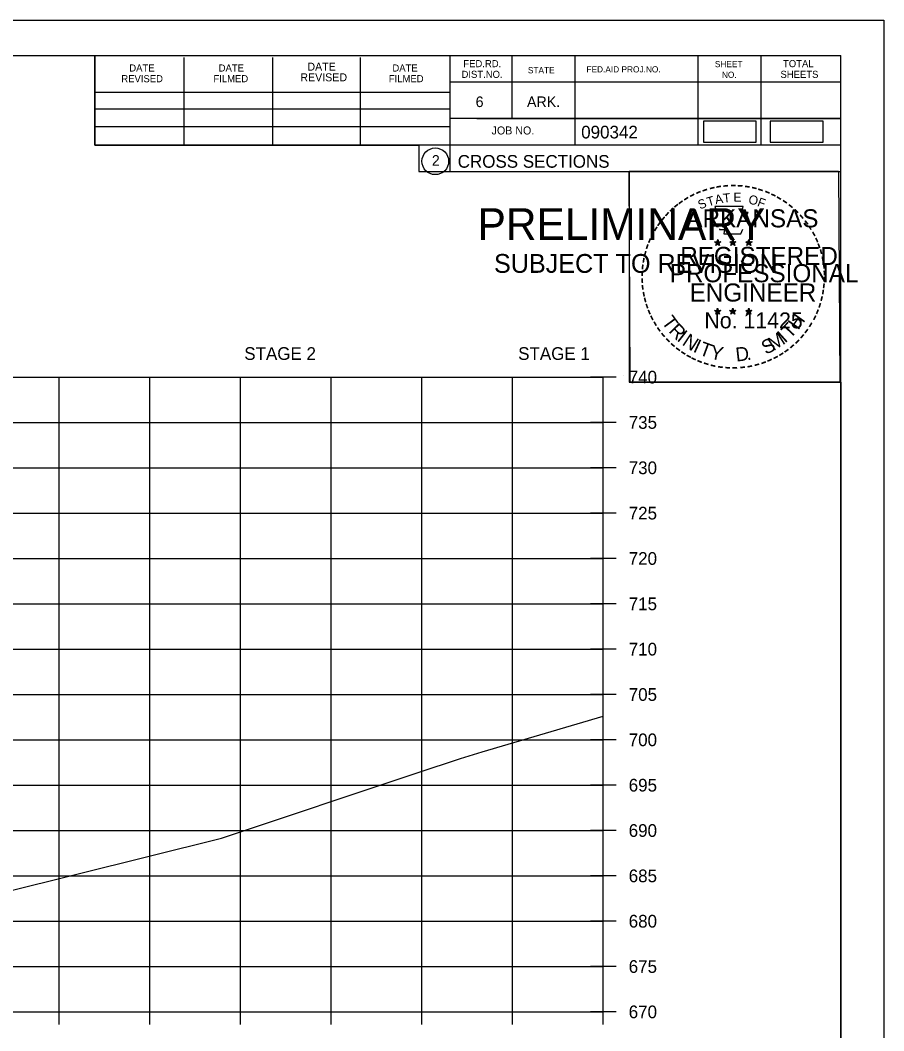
# Model space of a CAD drawing. Extents: x 1370515 to 1370849, y 383299 to 386073.
# Drawn here: x 1370753.5 to 1370848.7, y 383828 to 383939.4 of the extents above; entities that cross this region are included whole.
import ezdxf

# ---------------------------------------------------------------- set-up
doc = ezdxf.new("R2010")
doc.units = 0
for name, color, linetype in [('R_Axis', 7, 'Continuous'), ('R_Axis Annot', 7, 'Continuous'), ('R_Border', 7, 'Continuous'), ('R_Border PE', 7, 'Continuous'), ('R_Border Prem', 7, 'Continuous'), ('R_Detour', 7, 'Continuous'), ('R_Exist Surface', 7, 'Continuous'), ('R_Grid', 7, 'Continuous'), ('R_No Plot', 7, 'Continuous')]:
    doc.layers.add(name, color=color, linetype=linetype)

msp = doc.modelspace()

# ---------------------------------------------------------------- linework, layer by layer
at = {"layer": 'R_Axis'}
for p, q in [((1370819.2, 383900.08), (1370816.4, 383900.08)), ((1370817.8, 383830.08), (1370817.8, 383900.08)), ((1370819.2, 383895.08), (1370816.4, 383895.08)), ((1370819.2, 383890.08), (1370816.4, 383890.08)), ((1370819.2, 383885.08), (1370816.4, 383885.08)), ((1370819.2, 383880.08), (1370816.4, 383880.08)), ((1370819.2, 383875.08), (1370816.4, 383875.08)), ((1370819.2, 383870.08), (1370816.4, 383870.08)), ((1370819.2, 383865.08), (1370816.4, 383865.08)), ((1370819.2, 383860.08), (1370816.4, 383860.08)), ((1370819.2, 383855.08), (1370816.4, 383855.08)), ((1370819.2, 383850.08), (1370816.4, 383850.08)), ((1370819.2, 383845.08), (1370816.4, 383845.08)), ((1370819.2, 383840.08), (1370816.4, 383840.08)), ((1370819.2, 383835.08), (1370816.4, 383835.08)), ((1370757.8, 383828.68), (1370757.8, 383831.48)), ((1370767.8, 383828.68), (1370767.8, 383831.48)), ((1370777.8, 383828.68), (1370777.8, 383831.48)), ((1370787.8, 383828.68), (1370787.8, 383831.48)), ((1370797.8, 383828.68), (1370797.8, 383831.48)), ((1370807.8, 383828.68), (1370807.8, 383831.48)), ((1370817.8, 383828.68), (1370817.8, 383831.48)), ((1370537.8, 383830.08), (1370817.8, 383830.08)), ((1370819.2, 383830.08), (1370816.4, 383830.08))]:
    msp.add_line(p, q, dxfattribs=at)
at = {"layer": 'R_Border'}
for p, q in [((1370527.8, 383935.54), (1370843.98, 383935.54)), ((1370761.72, 383925.66), (1370761.72, 383935.54)), ((1370800.88, 383935.54), (1370800.88, 383922.74)), ((1370807.72, 383935.54), (1370807.72, 383928.6)), ((1370814.66, 383935.54), (1370814.66, 383925.66)), ((1370828.24, 383935.54), (1370828.24, 383925.66)), ((1370835.18, 383935.54), (1370835.18, 383925.66)), ((1370843.98, 383730.08), (1370843.98, 383935.54)), ((1370771.58, 383925.66), (1370771.58, 383935.34)), ((1370781.34, 383925.66), (1370781.34, 383935.34)), ((1370791.02, 383925.66), (1370791.02, 383935.34)), ((1370843.98, 383932.6), (1370800.88, 383932.6)), ((1370843.98, 383932.62), (1370843.98, 383932.62)), ((1370761.72, 383931.52), (1370800.88, 383931.52)), ((1370761.72, 383929.66), (1370800.88, 383929.66)), ((1370761.72, 383925.66), (1370761.72, 383927.72)), ((1370761.72, 383927.72), (1370800.88, 383927.72)), ((1370843.98, 383928.6), (1370800.88, 383928.6)), ((1370803.84, 383928.6), (1370843.98, 383928.6)), ((1370843.98, 383925.66), (1370761.72, 383925.66)), ((1370800.88, 383922.74), (1370843.98, 383922.74))]:
    msp.add_line(p, q, dxfattribs=at)
msp.add_circle((1370799.27, 383923.88), 1.47, dxfattribs=at)
at = {"layer": 'R_Border PE'}
for p, q in [((1370830.07, 383915), (1370830.42, 383914.89)), ((1370830.07, 383915), (1370830.32, 383914.95)), ((1370830.07, 383915), (1370830.3, 383914.88)), ((1370830.2, 383914.59), (1370830.42, 383914.89)), ((1370830.2, 383914.59), (1370830.33, 383914.84)), ((1370830.2, 383914.59), (1370830.41, 383914.81)), ((1370830.42, 383915.25), (1370830.37, 383915)), ((1370830.63, 383914.59), (1370830.41, 383914.81)), ((1370830.42, 383914.89), (1370830.42, 383915.25)), ((1370830.42, 383915.25), (1370830.46, 383915)), ((1370830.76, 383915), (1370830.42, 383914.89)), ((1370830.63, 383914.59), (1370830.42, 383914.89)), ((1370830.76, 383915), (1370830.48, 383914.95)), ((1370830.63, 383914.59), (1370830.49, 383914.88)), ((1370830.76, 383915), (1370830.56, 383914.9)), ((1370831.74, 383915), (1370832.09, 383914.89)), ((1370831.74, 383915), (1370831.99, 383914.95)), ((1370831.74, 383915), (1370831.97, 383914.88)), ((1370831.87, 383914.59), (1370832.09, 383914.89)), ((1370831.87, 383914.59), (1370832, 383914.84)), ((1370831.87, 383914.59), (1370832.08, 383914.81)), ((1370832.09, 383915.25), (1370832.04, 383915)), ((1370832.3, 383914.59), (1370832.08, 383914.81)), ((1370832.09, 383914.89), (1370832.09, 383915.25)), ((1370832.09, 383915.25), (1370832.13, 383915)), ((1370832.43, 383915), (1370832.09, 383914.89)), ((1370832.3, 383914.59), (1370832.09, 383914.89)), ((1370832.43, 383915), (1370832.15, 383914.95)), ((1370832.3, 383914.59), (1370832.16, 383914.88)), ((1370832.43, 383915), (1370832.23, 383914.9)), ((1370833.5, 383914.99), (1370833.85, 383914.88)), ((1370833.5, 383914.99), (1370833.75, 383914.94)), ((1370833.5, 383914.99), (1370833.74, 383914.87)), ((1370833.63, 383914.58), (1370833.85, 383914.88)), ((1370833.63, 383914.58), (1370833.76, 383914.82)), ((1370833.63, 383914.58), (1370833.85, 383914.8)), ((1370833.85, 383915.24), (1370833.81, 383914.99)), ((1370833.85, 383914.88), (1370833.85, 383915.24)), ((1370833.85, 383915.24), (1370833.9, 383914.99)), ((1370834.2, 383914.99), (1370833.85, 383914.88)), ((1370834.06, 383914.58), (1370833.85, 383914.88)), ((1370834.06, 383914.58), (1370833.85, 383914.79)), ((1370834.2, 383914.99), (1370833.91, 383914.94)), ((1370834.06, 383914.58), (1370833.93, 383914.87)), ((1370834.2, 383914.99), (1370833.99, 383914.89)), ((1370830.41, 383907.68), (1370830.37, 383907.43)), ((1370830.41, 383907.32), (1370830.41, 383907.68)), ((1370830.41, 383907.68), (1370830.46, 383907.43)), ((1370832.08, 383907.68), (1370832.04, 383907.43)), ((1370832.08, 383907.32), (1370832.08, 383907.68)), ((1370832.08, 383907.68), (1370832.13, 383907.43)), ((1370833.85, 383907.67), (1370833.81, 383907.42)), ((1370833.85, 383907.31), (1370833.85, 383907.67)), ((1370833.85, 383907.67), (1370833.9, 383907.42)), ((1370830.06, 383907.43), (1370830.41, 383907.32)), ((1370830.06, 383907.43), (1370830.32, 383907.38)), ((1370830.06, 383907.43), (1370830.3, 383907.3)), ((1370830.2, 383907.02), (1370830.41, 383907.32)), ((1370830.2, 383907.02), (1370830.32, 383907.26)), ((1370830.2, 383907.02), (1370830.41, 383907.24)), ((1370830.76, 383907.43), (1370830.41, 383907.32)), ((1370830.62, 383907.02), (1370830.41, 383907.32)), ((1370830.62, 383907.02), (1370830.41, 383907.23)), ((1370830.76, 383907.43), (1370830.47, 383907.38)), ((1370830.62, 383907.02), (1370830.49, 383907.31)), ((1370830.76, 383907.43), (1370830.55, 383907.32)), ((1370831.73, 383907.43), (1370832.08, 383907.32)), ((1370831.73, 383907.43), (1370831.98, 383907.38)), ((1370831.73, 383907.43), (1370831.97, 383907.3)), ((1370831.86, 383907.02), (1370832.08, 383907.32)), ((1370831.86, 383907.02), (1370831.99, 383907.26)), ((1370831.86, 383907.02), (1370832.08, 383907.24)), ((1370832.43, 383907.43), (1370832.08, 383907.32)), ((1370832.29, 383907.02), (1370832.08, 383907.32)), ((1370832.29, 383907.02), (1370832.08, 383907.23)), ((1370832.43, 383907.43), (1370832.14, 383907.38)), ((1370832.29, 383907.02), (1370832.16, 383907.31)), ((1370832.43, 383907.43), (1370832.22, 383907.32)), ((1370833.5, 383907.42), (1370833.85, 383907.31)), ((1370833.5, 383907.42), (1370833.75, 383907.37)), ((1370833.5, 383907.42), (1370833.74, 383907.29)), ((1370833.63, 383907.01), (1370833.85, 383907.31)), ((1370833.63, 383907.01), (1370833.76, 383907.25)), ((1370833.63, 383907.01), (1370833.85, 383907.23)), ((1370834.19, 383907.42), (1370833.85, 383907.31)), ((1370834.06, 383907.01), (1370833.85, 383907.31)), ((1370834.06, 383907.01), (1370833.85, 383907.22)), ((1370834.19, 383907.42), (1370833.91, 383907.37)), ((1370834.06, 383907.01), (1370833.92, 383907.3)), ((1370834.19, 383907.42), (1370833.99, 383907.31))]:
    msp.add_line(p, q, dxfattribs=at)
for points in [[(1370830.11, 383918.88), (1370830.38, 383918.05)], [(1370833.62, 383917.96), (1370833.76, 383918.24), (1370833.08, 383918.22), (1370833.22, 383918.88), (1370830.11, 383918.88)], [(1370830.6, 383916.45), (1370830.6, 383916.37), (1370831.16, 383916.35), (1370831.11, 383915.88), (1370832.98, 383915.88), (1370833.18, 383916.41)], [(1370830.42, 383915.25), (1370830.63, 383914.59), (1370830.07, 383915), (1370830.76, 383915), (1370830.2, 383914.59), (1370830.42, 383915.25)], [(1370832.09, 383915.25), (1370832.3, 383914.59), (1370831.74, 383915), (1370832.43, 383915), (1370831.87, 383914.59), (1370832.09, 383915.25)], [(1370833.85, 383915.24), (1370834.06, 383914.58), (1370833.5, 383914.99), (1370834.2, 383914.99), (1370833.63, 383914.58), (1370833.85, 383915.24)], [(1370830.41, 383907.68), (1370830.62, 383907.02), (1370830.06, 383907.43), (1370830.76, 383907.43), (1370830.2, 383907.02), (1370830.41, 383907.68)], [(1370832.08, 383907.68), (1370832.29, 383907.02), (1370831.73, 383907.43), (1370832.43, 383907.43), (1370831.86, 383907.02), (1370832.08, 383907.68)], [(1370833.85, 383907.67), (1370834.06, 383907.01), (1370833.5, 383907.42), (1370834.19, 383907.42), (1370833.63, 383907.01), (1370833.85, 383907.67)]]:
    msp.add_lwpolyline(points, dxfattribs=at)
for centre, radius in [((1370830.41, 383914.89), 0.172), ((1370830.41, 383914.89), 0.145), ((1370830.41, 383914.89), 0.116), ((1370830.41, 383914.89), 0.0991), ((1370830.41, 383914.89), 0.0747), ((1370830.41, 383914.89), 0.0495), ((1370830.41, 383914.89), 0.0296), ((1370832.08, 383914.89), 0.172), ((1370832.08, 383914.89), 0.145), ((1370832.08, 383914.89), 0.116), ((1370832.08, 383914.89), 0.0991), ((1370832.08, 383914.89), 0.0747), ((1370832.08, 383914.89), 0.0495), ((1370832.08, 383914.89), 0.0296), ((1370833.85, 383914.88), 0.172), ((1370833.85, 383914.88), 0.145), ((1370833.85, 383914.88), 0.116), ((1370833.85, 383914.88), 0.0991), ((1370833.85, 383914.88), 0.0747), ((1370833.85, 383914.88), 0.0495), ((1370833.85, 383914.88), 0.0296), ((1370830.41, 383907.32), 0.172), ((1370830.41, 383907.32), 0.145), ((1370830.41, 383907.32), 0.116), ((1370830.41, 383907.32), 0.0991), ((1370830.41, 383907.32), 0.0747), ((1370830.41, 383907.32), 0.0495), ((1370830.41, 383907.32), 0.0296), ((1370832.08, 383907.32), 0.172), ((1370832.08, 383907.32), 0.145), ((1370832.08, 383907.32), 0.116), ((1370832.08, 383907.32), 0.0991), ((1370832.08, 383907.32), 0.0747), ((1370832.08, 383907.32), 0.0495), ((1370832.08, 383907.32), 0.0296), ((1370833.85, 383907.31), 0.172), ((1370833.85, 383907.31), 0.145), ((1370833.85, 383907.31), 0.116), ((1370833.85, 383907.31), 0.0991), ((1370833.85, 383907.31), 0.0747), ((1370833.85, 383907.31), 0.0495), ((1370833.85, 383907.31), 0.0296)]:
    msp.add_circle(centre, radius, dxfattribs=at)
at = {"layer": 'R_Detour'}
for points in [[(1370828.84, 383925.98), (1370834.67, 383925.98), (1370834.67, 383928.29), (1370828.84, 383928.29)], [(1370836.22, 383925.98), (1370842.05, 383925.98), (1370842.05, 383928.29), (1370836.22, 383928.29)]]:
    msp.add_lwpolyline(points, close=True, dxfattribs=at)
at = {"layer": 'R_Exist Surface'}
msp.add_lwpolyline([(1370751.61, 383843.25), (1370775.7, 383849.25), (1370797.28, 383856.45), (1370802.06, 383858.04), (1370804.43, 383858.75), (1370817.8, 383862.68)], dxfattribs=at)
at = {"layer": 'R_Grid'}
for p, q in [((1370537.8, 383900.08), (1370817.8, 383900.08)), ((1370757.8, 383830.08), (1370757.8, 383900.08)), ((1370767.8, 383830.08), (1370767.8, 383900.08)), ((1370777.8, 383830.08), (1370777.8, 383900.08)), ((1370787.8, 383830.08), (1370787.8, 383900.08)), ((1370797.8, 383830.08), (1370797.8, 383900.08)), ((1370807.8, 383830.08), (1370807.8, 383900.08)), ((1370817.8, 383830.08), (1370817.8, 383900.08)), ((1370537.8, 383895.08), (1370817.8, 383895.08)), ((1370537.8, 383890.08), (1370817.8, 383890.08)), ((1370537.8, 383885.08), (1370817.8, 383885.08)), ((1370537.8, 383880.08), (1370817.8, 383880.08)), ((1370537.8, 383875.08), (1370817.8, 383875.08)), ((1370537.8, 383870.08), (1370817.8, 383870.08)), ((1370537.8, 383865.08), (1370817.8, 383865.08)), ((1370537.8, 383860.08), (1370817.8, 383860.08)), ((1370537.8, 383855.08), (1370817.8, 383855.08)), ((1370537.8, 383850.08), (1370817.8, 383850.08)), ((1370537.8, 383845.08), (1370817.8, 383845.08)), ((1370537.8, 383840.08), (1370817.8, 383840.08)), ((1370537.8, 383835.08), (1370817.8, 383835.08)), ((1370537.8, 383830.08), (1370817.8, 383830.08))]:
    msp.add_line(p, q, dxfattribs=at)
at = {"layer": 'R_No Plot'}
for p, q in [((1370515.4, 383939.44), (1370848.73, 383939.44)), ((1370820.02, 383900.29), (1370820.02, 383900.29))]:
    msp.add_line(p, q, dxfattribs=at)
for points in [[(1370515.39, 383939.44), (1370848.73, 383939.44), (1370848.73, 383726.1), (1370515.39, 383726.1)], [(1370761.72, 383935.54), (1370761.72, 383925.66), (1370797.45, 383925.66), (1370797.45, 383922.74), (1370820.65, 383922.74), (1370820.65, 383899.53), (1370843.98, 383899.53), (1370843.98, 383730.08), (1370527.8, 383730.08), (1370527.8, 383935.54)], [(1370820.65, 383922.78), (1370843.75, 383922.78), (1370843.87, 383899.53), (1370820.77, 383899.53)]]:
    msp.add_lwpolyline(points, close=True, dxfattribs=at)

# ---------------------------------------------------------------- texts
at = {"layer": 'R_Axis Annot'}
for s, p in [('STAGE 2', (1370778.2, 383901.98)), ('STAGE 1', (1370808.41, 383901.98)), ('740', (1370820.6, 383899.38)), ('735', (1370820.6, 383894.38)), ('730', (1370820.6, 383889.38)), ('725', (1370820.6, 383884.38)), ('720', (1370820.6, 383879.38)), ('715', (1370820.6, 383874.38)), ('710', (1370820.6, 383869.38)), ('705', (1370820.6, 383864.38)), ('700', (1370820.6, 383859.38)), ('695', (1370820.6, 383854.38)), ('690', (1370820.6, 383849.38)), ('685', (1370820.6, 383844.38)), ('680', (1370820.6, 383839.38)), ('675', (1370820.6, 383834.38)), ('670', (1370820.6, 383829.38))]:
    msp.add_text(s, height=1.4, dxfattribs=at).set_placement(p)
at = {"layer": 'R_Border'}
for s, height, p in [('DATE', 0.782, (1370765.52, 383933.78)), ('DATE', 0.782, (1370775.38, 383933.78)), ('DATE', 0.879, (1370785.16, 383933.88)), ('DATE', 0.782, (1370794.54, 383933.78)), ('FED.RD.', 0.782, (1370802.36, 383934.26)), ('STATE', 0.684, (1370809.48, 383933.58)), ('FED.AID PROJ.NO.', 0.684, (1370815.94, 383933.68)), ('SHEET', 0.684, (1370830.1, 383934.26)), ('TOTAL', 0.782, (1370837.62, 383934.26)), ('REVISED', 0.782, (1370764.64, 383932.6)), ('FILMED', 0.782, (1370774.8, 383932.6)), ('REVISED', 0.879, (1370784.38, 383932.7)), ('FILMED', 0.782, (1370794.14, 383932.6)), ('DIST.NO.', 0.782, (1370802.16, 383933.08)), ('NO.', 0.684, (1370830.88, 383933.08)), ('SHEETS', 0.782, (1370837.34, 383933.08)), ('6', 1.17, (1370803.72, 383929.86)), ('ARK.', 1.172, (1370809.38, 383929.86)), ('JOB NO.', 0.879, (1370805.48, 383926.84)), ('090342', 1.4, (1370815.36, 383926.4)), ('2', 1.17, (1370798.89, 383923.39)), ('CROSS SECTIONS', 1.4, (1370801.74, 383923.17))]:
    msp.add_text(s, height=height, rotation=360, dxfattribs=at).set_placement(p)
at = {"layer": 'R_Border PE'}
for s, height, rotation, p in [('-', 1.6, 13.6301, (1370829.61, 383920.25)), ('-', 1.6, 10.2193, (1370830.28, 383920.41)), ('-', 1.6, 5.8968, (1370831.01, 383920.52)), ('-', 1.6, 0.1862, (1370831.78, 383920.59)), ('-', 1.6, 357.743, (1370832.51, 383920.58)), ('-', 1.6, 352.1617, (1370833.25, 383920.52)), ('-', 1.6, 347.2049, (1370833.97, 383920.41)), ('-', 1.6, 34.0636, (1370826.99, 383919.05)), ('-', 1.6, 28.7918, (1370827.59, 383919.42)), ('-', 1.6, 24.3072, (1370828.22, 383919.74)), ('-', 1.6, 19.1761, (1370828.86, 383920)), ('T', 1, 16.4036, (1370829.38, 383918.89)), ('A', 1, 11.2132, (1370830.2, 383919.14)), ('T', 1, 6.0228, (1370831.05, 383919.3)), ('E', 1, 0.8323, (1370832.16, 383919.41)), ('O', 1, 350.4515, (1370833.76, 383919.2)), ('F', 1, 340.0707, (1370834.71, 383918.98)), ('-', 1.6, 342.3362, (1370834.61, 383920.25)), ('-', 1.6, 337.8551, (1370835.34, 383920.03)), ('-', 1.6, 334.1211, (1370835.97, 383919.76)), ('-', 1.6, 329.6409, (1370836.55, 383919.47)), ('-', 1.6, 42.9622, (1370825.5, 383917.86)), ('-', 1.6, 38.9507, (1370825.94, 383918.28)), ('-', 1.6, 36.2317, (1370826.41, 383918.65)), ('S', 1, 21.594, (1370828.46, 383918.56)), ('-', 1.6, 325.8627, (1370837.19, 383919.11)), ('-', 1.6, 320.5297, (1370837.8, 383918.69)), ('-', 1.6, 50.6142, (1370824.65, 383916.89)), ('-', 1.6, 48.423, (1370825.06, 383917.38)), ('ARKANSAS', 2, 360, (1370826.96, 383916.59)), ('-', 1.6, 315.5786, (1370838.4, 383918.2)), ('-', 1.6, 309.8797, (1370838.97, 383917.65)), ('-', 1.6, 58.0706, (1370823.92, 383915.8)), ('-', 1.6, 54.2325, (1370824.24, 383916.33)), ('-', 1.6, 306.6522, (1370839.5, 383917.05)), ('-', 1.4, 303.6753, (1370839.98, 383916.48)), ('-', 1.6, 67.7743, (1370823.34, 383914.58)), ('-', 1.6, 62.8713, (1370823.6, 383915.19)), ('-', 1.6, 299.6684, (1370840.3, 383915.87)), ('-', 1.6, 294.6628, (1370840.63, 383915.26)), ('-', 1.6, 72.3945, (1370823.12, 383913.95)), ('REGISTERED', 2, 360, (1370826.28, 383912.44)), ('DWB', 0.01, 360, (1370830.4, 383914.88)), ('DWB', 0.01, 360, (1370832.07, 383914.88)), ('DWB', 0.01, 360, (1370833.84, 383914.87)), ('-', 1.6, 290.5728, (1370840.88, 383914.68)), ('-', 1.6, 81.2013, (1370822.8, 383912.52)), ('-', 1.6, 75.461, (1370822.93, 383913.23)), ('-', 1.6, 285.1233, (1370841.12, 383914.1)), ('-', 1.6, 280.5493, (1370841.32, 383913.36)), ('-', 1.6, 85.1863, (1370822.72, 383911.83)), ('PROFESSIONAL', 2, 360, (1370825.13, 383910.54)), ('-', 1.6, 276.5962, (1370841.48, 383912.59)), ('-', 1.6, 94.1959, (1370822.73, 383910.4)), ('-', 1.6, 89.0622, (1370822.69, 383911.13)), ('-', 1.6, 274.3301, (1370841.54, 383911.87)), ('-', 1.6, 269.9407, (1370841.57, 383911.24)), ('-', 1.6, 98.9479, (1370822.8, 383909.73)), ('ENGINEER', 2, 360, (1370827.32, 383908.41)), ('-', 1.6, 263.5172, (1370841.55, 383910.57)), ('-', 1.6, 101.7149, (1370822.94, 383909)), ('-', 1.6, 105.4578, (1370823.1, 383908.41)), ('-', 1.6, 255.7626, (1370841.37, 383909.24)), ('-', 1.6, 260.9953, (1370841.48, 383909.92)), ('-', 1.6, 109.0874, (1370823.31, 383907.78)), ('-', 1.6, 114.0643, (1370823.57, 383907.18)), ('-', 1.6, 247.8887, (1370840.97, 383907.85)), ('-', 1.6, 252.8681, (1370841.19, 383908.52)), ('-', 1.6, 115.7288, (1370823.87, 383906.56)), ('T', 1.54, 306.0406, (1370824.17, 383906.15)), ('No. 11425', 1.757, 360, (1370828.95, 383905.46)), ('DWB', 0.01, 360, (1370830.4, 383907.31)), ('DWB', 0.01, 360, (1370832.07, 383907.31)), ('DWB', 0.01, 360, (1370833.83, 383907.3)), ('H', 1.54, 54.6088, (1370839.29, 383905.19)), ('-', 1.6, 244.6197, (1370840.71, 383907.22)), ('-', 1.6, 120.4471, (1370824.23, 383905.98)), ('-', 1.6, 125.8934, (1370824.63, 383905.41)), ('R', 1.54, 314.005, (1370824.93, 383905.11)), ('T', 1.54, 46.6444, (1370838.4, 383904.25)), ('-', 1.6, 233.8452, (1370839.91, 383905.81)), ('-', 1.6, 239.0712, (1370840.31, 383906.47)), ('-', 1.6, 130.7181, (1370825.09, 383904.86)), ('-', 1.6, 134.2238, (1370825.61, 383904.32)), ('I', 1.54, 321.9694, (1370825.83, 383904.17)), ('N', 1.54, 326.5002, (1370826.4, 383903.7)), ('I', 1.54, 335.3603, (1370827.61, 383902.92)), ('S', 1.54, 26.9312, (1370835.72, 383902.52)), ('M', 1.54, 32.6563, (1370836.56, 383902.92)), ('I', 1.54, 42.1136, (1370837.84, 383903.77)), ('-', 1.6, 225.7653, (1370839, 383904.68)), ('-', 1.6, 231.2538, (1370839.48, 383905.25)), ('-', 1.6, 138.9338, (1370826.14, 383903.85)), ('-', 1.6, 144.6463, (1370826.69, 383903.45)), ('T', 1.54, 339.8912, (1370828.27, 383902.59)), ('Y', 1.54, 347.8556, (1370829.49, 383902.14)), ('D', 1.54, 6.3969, (1370832.47, 383901.79)), ('-', 1.6, 215.7363, (1370837.93, 383903.7)), ('-', 1.6, 221.0851, (1370838.48, 383904.18)), ('-', 1.6, 148.0898, (1370827.25, 383903.08)), ('-', 1.6, 151.5704, (1370827.83, 383902.75)), ('-', 1.6, 154.6002, (1370828.35, 383902.5)), ('-', 1.6, 158.5612, (1370828.98, 383902.25)), ('.', 1.54, 13.7642, (1370833.66, 383901.91)), ('-', 1.6, 204.2516, (1370836.21, 383902.65)), ('-', 1.6, 207.3568, (1370836.84, 383902.97)), ('-', 1.6, 212.2491, (1370837.4, 383903.32)), ('-', 1.6, 162.7983, (1370829.67, 383902.04)), ('-', 1.6, 167.5555, (1370830.38, 383901.87)), ('-', 1.6, 173.1155, (1370831.15, 383901.76)), ('-', 1.6, 176.5183, (1370831.9, 383901.71)), ('-', 1.6, 181.5918, (1370832.64, 383901.73)), ('-', 1.6, 185.8167, (1370833.45, 383901.81)), ('-', 1.6, 191.2858, (1370834.19, 383901.94)), ('-', 1.6, 195.4743, (1370834.92, 383902.14)), ('-', 1.6, 200.7184, (1370835.6, 383902.38))]:
    msp.add_text(s, height=height, rotation=rotation, dxfattribs=at).set_placement(p)
at = {"layer": 'R_Border Prem'}
for s, height, p in [('PRELIMINARY', 3.5, (1370803.93, 383915.21)), ('DWB', 0.01, (1370804.68, 383917.06)), ('SUBJECT TO REVISION', 2.0751, (1370805.74, 383911.58))]:
    msp.add_text(s, height=height, rotation=360, dxfattribs=at).set_placement(p)
at = {"layer": 'R_No Plot'}
for p in [(1370802.02, 383857.99), (1370775.65, 383849.2)]:
    msp.add_text('+', height=0.1, dxfattribs=at).set_placement(p)

doc.saveas('drawing.dxf')
